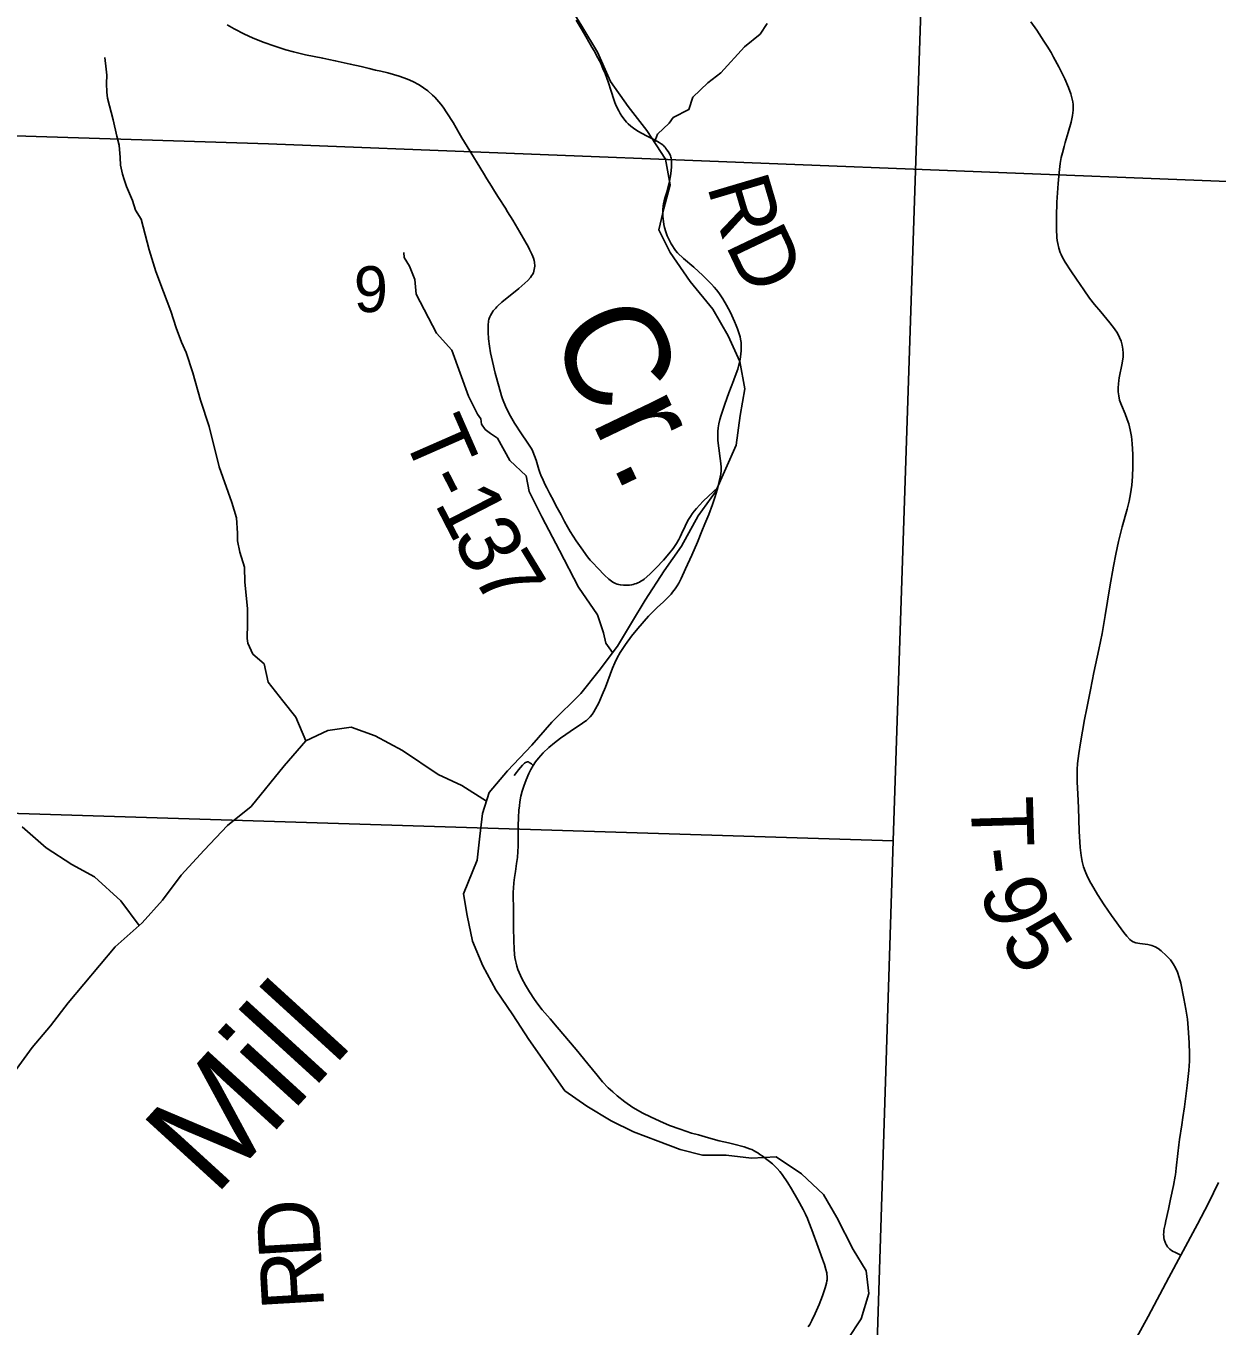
# Model space of a CAD drawing. Extents: x 6.3 to 40.3, y 9 to 31.
# Drawn here: x 11.496 to 12.585, y 26.729 to 27.918 of the extents above; entities that cross this region are included whole.
import ezdxf

# ---------------------------------------------------------------- set-up
doc = ezdxf.new("R2010")
doc.units = 0
for name, color, linetype in [('Default', 7, 'Continuous'), ('GM_X_Minor_River', 7, 'Continuous'), ('GM_X_Minor_River_Text', 7, 'Continuous'), ('GM_X_Section', 7, 'Continuous'), ('GM_X_Section_Text', 7, 'Continuous'), ('GM_X_State_Route', 7, 'Continuous'), ('GM_X_Township_Road', 7, 'Continuous'), ('GM_X_Township_Road_Text', 7, 'Continuous')]:
    doc.layers.add(name, color=color, linetype=linetype)

msp = doc.modelspace()

# ---------------------------------------------------------------- linework, layer by layer
at = {"layer": 'Default'}
msp.add_lwpolyline([(13.1323, 29.9457), (8.4446, 29.9457), (8.4446, 27.9161), (8.9627, 27.9002), (9.9314, 27.8681), (10.145, 27.8635), (10.7129, 27.8423), (11.7175, 27.8106), (12.5872, 27.7766), (13.0625, 27.76), (13.0974, 28.6191), (13.1136, 29.1637), (13.1156, 29.231), (13.116, 29.2473), (13.13, 29.8856)], close=True, dxfattribs=at)
msp.add_lwpolyline([(12.5872, 27.7766), (11.7175, 27.8106), (10.7129, 27.8423), (10.145, 27.8635), (9.9314, 27.8681), (8.9627, 27.9002), (8.4446, 27.9161), (8.4446, 23.1457)], dxfattribs=at)
at = {"layer": 'GM_X_Minor_River'}
for points in [[(12.2471, 26.7169), (12.2596, 26.7361), (12.2668, 26.7591), (12.2642, 26.7799), (12.2524, 26.7995), (12.2373, 26.8286), (12.2252, 26.8497), (12.2051, 26.8686), (12.182, 26.8841), (12.1593, 26.883), (12.1362, 26.8856), (12.1146, 26.8856), (12.0942, 26.8909), (12.0741, 26.8984), (12.0514, 26.9071), (12.031, 26.9169), (12.0086, 26.9305), (11.9886, 26.9445), (11.9556, 26.9913), (11.9409, 27.014), (11.9254, 27.037), (11.9136, 27.0589), (11.9042, 27.0815), (11.8992, 27.1049), (11.8958, 27.1246), (11.9083, 27.1555), (11.911, 27.1774), (11.9132, 27.1982), (11.9193, 27.2174), (11.9363, 27.2371), (11.9583, 27.2608), (11.9768, 27.2816), (12.0033, 27.308), (12.02, 27.3288), (12.0367, 27.3511), (12.0495, 27.3726), (12.062, 27.3933), (12.0794, 27.4201), (12.0953, 27.4428), (12.1105, 27.4704), (12.1264, 27.4923), (12.1453, 27.5349), (12.1491, 27.5621), (12.1533, 27.5866), (12.1487, 27.6116), (12.1381, 27.635), (12.1241, 27.6595), (12.1033, 27.6848), (12.0848, 27.7112), (12.0745, 27.732), (12.0791, 27.7516), (12.0848, 27.7732), (12.0806, 27.7966), (12.0636, 27.823), (12.0465, 27.8449), (12.0303, 27.8676), (12.0185, 27.8944), (12.0041, 27.9182), (11.9886, 27.9438)], [(12.0705, 27.8122), (12.0733, 27.8196), (12.0839, 27.8296), (12.0876, 27.8346), (12.1019, 27.842), (12.1056, 27.8534), (12.1195, 27.8665), (12.1312, 27.8757), (12.153, 27.8995), (12.1673, 27.911), (12.1736, 27.9206)], [(11.7516, 27.2646), (11.7425, 27.2862), (11.7306, 27.3013), (11.7171, 27.3183), (11.7135, 27.3349), (11.7032, 27.3439), (11.6985, 27.3538), (11.6981, 27.3583), (11.6983, 27.372), (11.6982, 27.3857), (11.696, 27.4096), (11.6955, 27.4236), (11.6912, 27.4372), (11.6892, 27.4475), (11.6891, 27.4547), (11.6882, 27.4687), (11.6839, 27.4827), (11.6725, 27.5153), (11.6634, 27.552), (11.6555, 27.5763), (11.6484, 27.6013), (11.6422, 27.6198), (11.6379, 27.6293), (11.6332, 27.6425), (11.6281, 27.6576), (11.6214, 27.6754), (11.6144, 27.694), (11.6085, 27.7137), (11.601, 27.7417), (11.596, 27.75), (11.5932, 27.7587), (11.5878, 27.7715), (11.5854, 27.778), (11.5839, 27.7829), (11.5823, 27.7912), (11.5818, 27.7981), (11.5809, 27.8095), (11.5789, 27.8178), (11.5754, 27.8326), (11.5702, 27.8523), (11.5698, 27.858), (11.5693, 27.8659), (11.5696, 27.8735), (11.5692, 27.8789), (11.5679, 27.8895)], [(12.0323, 27.3453), (12.0323, 27.3453), (12.0262, 27.3538), (12.0239, 27.3633), (12.0184, 27.3799), (12.001, 27.4052), (11.9836, 27.4388), (11.9677, 27.4694), (11.956, 27.4928), (11.9532, 27.5069), (11.9383, 27.5211), (11.927, 27.5415), (11.9205, 27.5456), (11.9156, 27.5494), (11.9125, 27.5543), (11.9117, 27.5592), (11.9086, 27.5634), (11.9004, 27.58), (11.8852, 27.622), (11.8713, 27.6374), (11.8527, 27.6733), (11.8514, 27.6866), (11.8491, 27.6927), (11.8464, 27.6987), (11.8417, 27.7066), (11.8413, 27.7112)], [(11.9168, 27.2094), (11.8943, 27.2239), (11.8727, 27.2337), (11.8402, 27.2559), (11.8152, 27.2692), (11.7932, 27.2771), (11.7717, 27.2741), (11.7516, 27.2646), (11.7319, 27.2416), (11.7016, 27.2046), (11.68, 27.1873), (11.6588, 27.1646), (11.6376, 27.1416), (11.6206, 27.1189), (11.6021, 27.0982), (11.5774, 27.0763), (11.5343, 27.0249), (11.518, 27.0038), (11.5014, 26.9842), (11.4794, 26.954)], [(11.5994, 27.0958), (11.5824, 27.1182), (11.5585, 27.1401), (11.5377, 27.1514), (11.5142, 27.1669), (11.4923, 27.1861)]]:
    msp.add_lwpolyline(points, dxfattribs=at)
at = {"layer": 'GM_X_Section'}
for points in [[(11.3334, 28.2025), (12.3225, 28.18), (12.2889, 27.1733), (11.3031, 27.2038)], [(11.3031, 27.2038), (12.2889, 27.1733), (12.2638, 26.3888), (12.2636, 26.3793), (12.255, 26.3481), (12.2521, 26.3409), (12.2402, 26.3255), (12.2343, 26.3163), (12.218, 26.293), (12.2028, 26.2726), (12.1883, 26.2538), (12.1742, 26.2366), (12.1608, 26.2201), (12.1526, 26.2116), (12.1361, 26.1988), (12.0826, 26.1813), (11.2666, 26.2073)]]:
    msp.add_lwpolyline(points, close=True, dxfattribs=at)
at = {"layer": 'GM_X_State_Route'}
msp.add_lwpolyline([(12.4788, 26.6591), (12.5221, 26.7381), (12.5412, 26.7737), (12.5522, 26.7942), (12.5674, 26.8224), (12.5773, 26.8417), (12.5865, 26.8607)], dxfattribs=at)
at = {"layer": 'GM_X_Township_Road'}
for points in [[(12.1284, 27.4963), (12.12, 27.4883), (12.1152, 27.4837), (12.1118, 27.4802), (12.109, 27.4772), (12.1069, 27.4747), (12.1051, 27.4723), (12.1034, 27.4697), (12.1011, 27.4661), (12.0986, 27.4611), (12.0953, 27.4538), (12.0942, 27.4511), (12.0929, 27.4488), (12.0907, 27.445), (12.0876, 27.4404), (12.0838, 27.4356), (12.0789, 27.43), (12.0722, 27.423), (12.0662, 27.417), (12.0612, 27.4126), (12.0598, 27.4116), (12.0582, 27.4106), (12.0568, 27.4098), (12.0555, 27.4091), (12.0541, 27.4086), (12.0526, 27.4081), (12.0512, 27.4077), (12.0497, 27.4073), (12.0479, 27.4071), (12.0461, 27.4069), (12.0443, 27.4069), (12.0424, 27.4069), (12.0394, 27.4072), (12.0379, 27.4075), (12.0364, 27.4079), (12.035, 27.4084), (12.0337, 27.409), (12.0324, 27.4098), (12.0312, 27.4106), (12.0289, 27.4126), (12.025, 27.4161), (12.0187, 27.4225), (12.0141, 27.4274), (12.0119, 27.4298), (12.0094, 27.433), (12.0035, 27.4411), (11.9989, 27.4477), (11.9936, 27.456), (11.991, 27.4603), (11.9883, 27.4651), (11.9851, 27.4712), (11.9805, 27.48), (11.9783, 27.4844), (11.975, 27.4904), (11.9721, 27.4959), (11.9707, 27.4987), (11.9687, 27.5029), (11.9667, 27.5077), (11.9657, 27.5102), (11.9648, 27.5129), (11.9623, 27.5212), (11.9609, 27.5253), (11.9593, 27.5293), (11.9583, 27.5314), (11.9573, 27.5331), (11.9542, 27.5378), (11.9489, 27.5453), (11.9426, 27.5552), (11.9389, 27.5615), (11.9352, 27.5687), (11.9327, 27.5743), (11.9317, 27.5773), (11.9307, 27.5801), (11.9281, 27.5889), (11.9249, 27.6008), (11.9223, 27.6116), (11.9207, 27.6194), (11.9198, 27.6256), (11.9189, 27.6322), (11.9184, 27.6383), (11.9184, 27.6435), (11.9185, 27.6456), (11.9187, 27.6474), (11.9189, 27.6489), (11.9191, 27.65), (11.9193, 27.6508), (11.9199, 27.6524), (11.9206, 27.6538), (11.9218, 27.6558), (11.9232, 27.6579), (11.9254, 27.6605), (11.9264, 27.6617), (11.9274, 27.6626), (11.9311, 27.6658), (11.9464, 27.6784), (11.952, 27.6833), (11.9548, 27.6857), (11.9573, 27.6885), (11.9582, 27.6898), (11.959, 27.691), (11.9598, 27.6927), (11.9603, 27.6941), (11.9607, 27.6956), (11.961, 27.6972), (11.9611, 27.6987), (11.9611, 27.7001), (11.961, 27.7011), (11.9608, 27.7025), (11.9605, 27.7041), (11.9599, 27.706), (11.9593, 27.7077), (11.9584, 27.7099), (11.9576, 27.7117), (11.9564, 27.7141), (11.9553, 27.7161), (11.9519, 27.722), (11.9473, 27.73), (11.9411, 27.7407), (11.9362, 27.7485), (11.9342, 27.7517), (11.9278, 27.7616), (11.9242, 27.7674), (11.9214, 27.7718), (11.9173, 27.7785), (11.9141, 27.7838), (11.8993, 27.8081), (11.8945, 27.8161), (11.892, 27.8204), (11.8864, 27.8301), (11.8808, 27.839), (11.8772, 27.8441), (11.8752, 27.8468), (11.8734, 27.8491), (11.8715, 27.8513), (11.8698, 27.8532), (11.8675, 27.8553), (11.8634, 27.859), (11.8594, 27.862), (11.8553, 27.8647), (11.8497, 27.8676), (11.8446, 27.8698), (11.8371, 27.8727), (11.8318, 27.8742), (11.8267, 27.8755), (11.8203, 27.877), (11.8154, 27.8781), (11.8095, 27.8796), (11.8022, 27.8813), (11.7923, 27.8836), (11.7786, 27.8866), (11.7726, 27.8879), (11.7671, 27.889), (11.7513, 27.8922), (11.7465, 27.8933), (11.7405, 27.8948), (11.7333, 27.8967), (11.7233, 27.8999), (11.7127, 27.9037), (11.7029, 27.9075), (11.6956, 27.911), (11.6862, 27.9158), (11.6798, 27.9196)], [(12.1428, 27.5939), (12.1435, 27.5958), (12.1467, 27.6046), (12.1482, 27.6098), (12.149, 27.6133), (12.1494, 27.6159), (12.1497, 27.6185), (12.1499, 27.6212), (12.15, 27.6239), (12.15, 27.6263), (12.1499, 27.6277), (12.1498, 27.6291), (12.1494, 27.6319), (12.1489, 27.634), (12.1484, 27.636), (12.1466, 27.6415), (12.1454, 27.6446), (12.1439, 27.6482), (12.1401, 27.6564), (12.1366, 27.663), (12.1332, 27.6688), (12.1295, 27.6743), (12.1274, 27.6771), (12.1253, 27.6796), (12.1229, 27.6822), (12.1207, 27.6844), (12.1148, 27.6903), (12.1065, 27.6979), (12.097, 27.7059), (12.0916, 27.711), (12.0899, 27.7131), (12.0885, 27.715), (12.0872, 27.7173), (12.086, 27.7193), (12.084, 27.723), (12.0823, 27.7266), (12.0809, 27.7303), (12.0798, 27.7341), (12.0791, 27.737), (12.0787, 27.7396), (12.0782, 27.7441), (12.0782, 27.7481), (12.0782, 27.7507), (12.0785, 27.7533), (12.079, 27.7562), (12.0795, 27.7584), (12.0805, 27.7619), (12.0818, 27.7665), (12.0839, 27.7747), (12.085, 27.7798), (12.0856, 27.7832), (12.086, 27.7865), (12.0862, 27.7892), (12.0863, 27.7914), (12.0863, 27.7932), (12.0863, 27.7948), (12.0861, 27.7962), (12.0859, 27.7975), (12.0857, 27.7986), (12.0852, 27.7998), (12.0846, 27.8011), (12.084, 27.8022), (12.0832, 27.8036), (12.082, 27.8052), (12.0811, 27.8065), (12.0803, 27.8075), (12.0795, 27.8083), (12.0788, 27.809), (12.0781, 27.8096), (12.0768, 27.8106), (12.075, 27.8118), (12.0734, 27.8128), (12.07, 27.8146), (12.0638, 27.8178), (12.0588, 27.8204), (12.056, 27.822), (12.0527, 27.8241), (12.0489, 27.8268), (12.0464, 27.829), (12.045, 27.8305), (12.0438, 27.832), (12.0408, 27.8361), (12.0393, 27.8384), (12.0379, 27.8409), (12.0357, 27.8455), (12.0343, 27.8486), (12.0334, 27.8512), (12.0309, 27.8588), (12.0282, 27.8673), (12.0254, 27.875), (12.0235, 27.8797), (12.0219, 27.8835), (12.0204, 27.8866), (12.0189, 27.8893), (12.0153, 27.8958), (12.0134, 27.8991), (12.0091, 27.9066), (12.0078, 27.9087), (12.0045, 27.9147), (11.9989, 27.9237)], [(12.4697, 27.1345), (12.4667, 27.1402), (12.4644, 27.1453), (12.463, 27.1495), (12.4618, 27.1543), (12.4608, 27.1598), (12.4601, 27.1672), (12.4592, 27.1821), (12.4588, 27.1926), (12.4584, 27.2032), (12.4578, 27.2162), (12.4573, 27.2267), (12.4572, 27.2328), (12.4572, 27.2384), (12.4576, 27.2439), (12.4587, 27.253), (12.4603, 27.2627), (12.4639, 27.2841), (12.466, 27.2944), (12.4695, 27.3113), (12.4726, 27.3271), (12.4771, 27.3483), (12.48, 27.3629), (12.4828, 27.3794), (12.4871, 27.4056), (12.4905, 27.4245), (12.4926, 27.4355), (12.4951, 27.447), (12.4972, 27.4555), (12.4985, 27.4603), (12.503, 27.4764), (12.5048, 27.4837), (12.5061, 27.4904), (12.5072, 27.4984), (12.5078, 27.5064), (12.5081, 27.5151), (12.508, 27.5269), (12.5076, 27.5362), (12.5073, 27.5398), (12.5069, 27.543), (12.5058, 27.5491), (12.5044, 27.5545), (12.503, 27.5585), (12.501, 27.5637), (12.4977, 27.5716), (12.4961, 27.5762), (12.4952, 27.5803), (12.4948, 27.5839), (12.4947, 27.5876), (12.495, 27.591), (12.4953, 27.5943), (12.4957, 27.5967), (12.4984, 27.6101), (12.4992, 27.6157), (12.4993, 27.6193), (12.4991, 27.623), (12.4984, 27.6266), (12.4974, 27.6302), (12.496, 27.6336), (12.494, 27.6374), (12.4913, 27.6416), (12.4872, 27.647), (12.4788, 27.6569), (12.4732, 27.6636), (12.4686, 27.6695), (12.4632, 27.677), (12.4565, 27.6868), (12.4514, 27.6945), (12.4464, 27.7024), (12.4436, 27.7072), (12.4426, 27.7094), (12.4418, 27.7112), (12.4404, 27.7153), (12.4394, 27.7195), (12.439, 27.7222), (12.4387, 27.7251), (12.4383, 27.7325), (12.4383, 27.7443), (12.4387, 27.7573), (12.4391, 27.7659), (12.4397, 27.7745), (12.4407, 27.7843), (12.4418, 27.7928), (12.4427, 27.7983), (12.4437, 27.8024), (12.4453, 27.8082), (12.4464, 27.8119), (12.4491, 27.821), (12.4518, 27.8306), (12.4531, 27.8367), (12.4534, 27.8391), (12.4536, 27.8416), (12.4537, 27.8441), (12.4536, 27.8465), (12.4534, 27.849), (12.4528, 27.8516), (12.4515, 27.8563), (12.4494, 27.8621), (12.4459, 27.8701), (12.4404, 27.8812), (12.4357, 27.8899), (12.4333, 27.8941), (12.4312, 27.8977), (12.4303, 27.899), (12.4268, 27.9047), (12.4204, 27.9145), (12.415, 27.9221)], [(12.1284, 27.4963), (12.1299, 27.5018), (12.1307, 27.5057), (12.1312, 27.5086), (12.1316, 27.512), (12.1316, 27.515), (12.1313, 27.5184), (12.1307, 27.5228), (12.1295, 27.5324), (12.1287, 27.5393), (12.1284, 27.5436), (12.1284, 27.5457), (12.1285, 27.5474), (12.1289, 27.551), (12.1295, 27.5545), (12.1304, 27.5584), (12.1317, 27.5626), (12.1349, 27.5727), (12.1387, 27.583), (12.1428, 27.5939)], [(11.9596, 27.2422), (11.9617, 27.2453), (11.9644, 27.2488), (11.9665, 27.2513), (11.9689, 27.2537), (11.9739, 27.2584), (11.9792, 27.2627), (11.9847, 27.2671), (11.9896, 27.2705), (11.9975, 27.276), (12.0036, 27.2799), (12.006, 27.2816), (12.0083, 27.2832), (12.0099, 27.2847), (12.0118, 27.2866), (12.0136, 27.2887), (12.0152, 27.291), (12.0168, 27.2938), (12.0196, 27.2994), (12.0228, 27.3067), (12.0257, 27.3136), (12.0301, 27.3252), (12.0323, 27.331), (12.0343, 27.3361), (12.0365, 27.3405), (12.0392, 27.3453), (12.044, 27.3526), (12.0497, 27.3604), (12.0553, 27.3675), (12.065, 27.3785), (12.073, 27.3865), (12.079, 27.3919), (12.0843, 27.3973), (12.0859, 27.3989), (12.0872, 27.4005), (12.0895, 27.4036), (12.0913, 27.4064), (12.0928, 27.4089), (12.0949, 27.413), (12.099, 27.4218), (12.1048, 27.4345), (12.11, 27.4464), (12.1139, 27.4563), (12.1168, 27.4631), (12.1204, 27.4717), (12.1238, 27.4809), (12.1262, 27.4881), (12.1284, 27.4963)], [(12.2112, 26.7285), (12.2126, 26.7308), (12.2146, 26.7344), (12.2176, 26.7409), (12.2212, 26.7492), (12.2244, 26.757), (12.2268, 26.7643), (12.228, 26.7686), (12.2284, 26.7706), (12.2285, 26.7716), (12.2287, 26.7727), (12.2287, 26.7739), (12.2285, 26.7751), (12.2283, 26.7765), (12.2281, 26.7779), (12.2273, 26.7811), (12.226, 26.7857), (12.2244, 26.7904), (12.2202, 26.8016), (12.2144, 26.8174), (12.2118, 26.8245), (12.2105, 26.8277), (12.2086, 26.8317), (12.2066, 26.8358), (12.2017, 26.8449), (12.1958, 26.855), (12.1925, 26.8604), (12.1874, 26.8679), (12.1864, 26.8693), (12.1853, 26.8707), (12.1828, 26.8734), (12.1806, 26.8757), (12.1786, 26.8776), (12.1758, 26.8799), (12.1734, 26.8816), (12.169, 26.8849), (12.167, 26.8864), (12.1651, 26.8877), (12.1634, 26.8887), (12.1618, 26.8896), (12.1595, 26.8907), (12.1576, 26.8915), (12.1552, 26.8924), (12.1526, 26.8932), (12.1432, 26.8956), (12.1384, 26.8969), (12.1299, 26.8989), (12.122, 26.901), (12.1171, 26.9023), (12.1108, 26.9041), (12.1045, 26.9059), (12.0941, 26.9093), (12.0842, 26.9128), (12.0754, 26.9166), (12.0671, 26.9206), (12.0599, 26.9242), (12.0509, 26.9293), (12.0435, 26.9344), (12.0366, 26.9398), (12.0324, 26.9437), (12.0283, 26.9473), (12.0232, 26.9527), (12.0181, 26.9588), (12.0097, 26.9692), (11.999, 26.9824), (11.9817, 27.0027), (11.9752, 27.0102), (11.9678, 27.0187), (11.9638, 27.0238), (11.9608, 27.0281), (11.9564, 27.035), (11.9525, 27.0412), (11.9493, 27.0471), (11.9467, 27.0527), (11.9456, 27.0556), (11.9447, 27.0586), (11.9441, 27.0612), (11.9435, 27.0638), (11.943, 27.0665), (11.9427, 27.0692), (11.9423, 27.0745), (11.9419, 27.0817), (11.9416, 27.0938), (11.9416, 27.1049), (11.9415, 27.1122), (11.9414, 27.1218), (11.9414, 27.1263), (11.9416, 27.1299), (11.942, 27.1347), (11.9426, 27.1396), (11.9435, 27.145), (11.9445, 27.1523), (11.9452, 27.158), (11.9456, 27.1633), (11.9458, 27.1682), (11.9459, 27.1734), (11.9458, 27.1792), (11.946, 27.187), (11.9462, 27.1946), (11.9465, 27.2011), (11.947, 27.2051), (11.9475, 27.2087), (11.9484, 27.2141), (11.9496, 27.2187), (11.9511, 27.2233), (11.9533, 27.229), (11.9557, 27.2348), (11.9575, 27.2383), (11.9596, 27.2422)], [(11.9422, 27.2328), (11.9443, 27.2356), (11.9463, 27.2381), (11.9479, 27.2401), (11.9498, 27.2423), (11.9509, 27.2434), (11.9518, 27.2442), (11.9527, 27.2448), (11.9534, 27.2451), (11.9544, 27.2453), (11.9553, 27.2453), (11.9561, 27.2449), (11.958, 27.2435), (11.9596, 27.2422)], [(12.5469, 26.8665), (12.5471, 26.8676), (12.5479, 26.8737), (12.5493, 26.8871), (12.5501, 26.8952), (12.5508, 26.9), (12.5529, 26.9134), (12.554, 26.9201), (12.5554, 26.9299), (12.5564, 26.9372), (12.5578, 26.9494), (12.5593, 26.963), (12.56, 26.9716), (12.5601, 26.9784), (12.5596, 26.9883), (12.5588, 27.002), (12.558, 27.01), (12.5567, 27.0192), (12.5547, 27.0289), (12.5519, 27.0429), (12.5506, 27.0483), (12.549, 27.053), (12.5472, 27.057), (12.545, 27.0607), (12.5425, 27.0642), (12.5387, 27.0682), (12.5342, 27.0725), (12.5312, 27.0748), (12.5285, 27.0763), (12.5256, 27.0774), (12.522, 27.0783), (12.5146, 27.0792), (12.5109, 27.0799), (12.5086, 27.0807), (12.507, 27.0816), (12.5055, 27.0828), (12.5026, 27.0859), (12.4998, 27.0893), (12.4886, 27.1049), (12.4819, 27.1146), (12.4758, 27.124), (12.4702, 27.1336), (12.4697, 27.1345)], [(12.5522, 26.7942), (12.5467, 26.7968), (12.545, 26.7976), (12.5436, 26.7986), (12.5421, 26.7996), (12.5413, 26.8003), (12.5407, 26.8009), (12.54, 26.8017), (12.5395, 26.8024), (12.5386, 26.804), (12.538, 26.8051), (12.5376, 26.8062), (12.5369, 26.8086), (12.5365, 26.8101), (12.5364, 26.8117), (12.5363, 26.8132), (12.5364, 26.8148), (12.5366, 26.8167), (12.5368, 26.8185), (12.5376, 26.8223), (12.5383, 26.8256), (12.5407, 26.8364), (12.5427, 26.8453), (12.5454, 26.8579), (12.5469, 26.8665)]]:
    msp.add_lwpolyline(points, dxfattribs=at)

# ---------------------------------------------------------------- texts
at = {"layer": 'GM_X_Minor_River_Text'}
for s, height, rotation, p in [('Cr.', 0.09472, 295.6, (11.973, 27.64)), ('Mill', 0.0947, 47.6106, (11.6681, 26.8468))]:
    msp.add_text(s, height=height, rotation=rotation, dxfattribs=at).set_placement(p)
at = {"layer": 'GM_X_Section_Text'}
msp.add_text('9', height=0.0419, rotation=0, dxfattribs=at).set_placement((11.7956, 27.6568))
at = {"layer": 'GM_X_Township_Road_Text'}
for s, rotation, p in [('R', 286.5105, (12.1183, 27.7723)), ('D', 295.4096, (12.1349, 27.7187)), ('T', 293.7005, (11.8394, 27.5452)), ('-', 297.2911, (11.8582, 27.5028)), ('1', 297.2539, (11.8689, 27.482)), ('3', 297.4127, (11.885, 27.4508)), ('7', 301.3008, (11.9031, 27.416)), ('T', 271.7059, (12.3599, 27.213)), ('-', 276.8278, (12.3616, 27.165)), ('9', 289.2619, (12.3674, 27.1287)), ('5', 303.1942, (12.3856, 27.0822)), ('D', 93.3459, (11.7659, 26.7925)), ('R', 93.348, (11.7686, 26.7459))]:
    msp.add_text(s, height=0.0568, rotation=rotation, dxfattribs=at).set_placement(p)

doc.saveas('drawing.dxf')
